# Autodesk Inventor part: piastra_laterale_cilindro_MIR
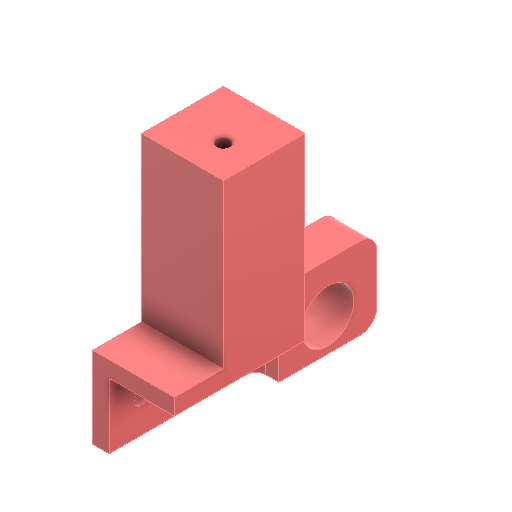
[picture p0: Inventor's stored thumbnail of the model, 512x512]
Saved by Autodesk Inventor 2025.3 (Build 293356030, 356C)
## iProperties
Created: 2025-09
Part Number: piastra_laterale_cilindro_MIR
Material: Plastica ABS
Document SubType Name: Modeling
Designer: R5800u
Density: 1.06 g/cm^3
Appearance: Liscia - Bianco
Author: R5800u
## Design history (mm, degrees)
derived "piastra_laterale_cilindro.ipt"
  sketch "Schizzo1"
    geometry: L1 (2.5, 10)-(-2.5, 10) reference; L2 (-2.5, 10)-(-2.5, -10) reference; L3 (-2.5, -10)-(2.5, -10) reference; L4 (2.5, -10)-(2.5, 10) reference; L5 (2.5, 10)-(-2.5, -10) reference; L6 (-2.5, 10)-(2.5, -10) reference; 1 further point
  sketch "Schizzo2"
    geometry: L1 (-50, 20)-(0, 20) reference; L2 (0, 0)-(-25, 0) reference; L3 (-25, 0)-(-25, 20) reference; L4 (-25, 20)-(0, 20) reference; L5 (0, 20)-(0, 0) reference; L6 (-30, 1)-(-30, 6.7) reference; L7 (-25, 0)-(-30, 0) reference; L8 (-30, 0)-(-30, 20) reference; L9 (-30, 20)-(-25, 20) reference; L10 (-25, 20)-(-25, 0) reference; 1 further point
  sketch "Schizzo3"
    geometry: C1 r 4 at (10, 10) reference; C2 r 8 at (10, 10) reference; 1 further point
  sketch "Schizzo4"
    geometry: L1 (2.5, -10)-(-2.5, -10) reference; L2 (-2.5, -10)-(-2.5, 10) reference; L3 (-2.5, 10)-(2.5, 10) reference; L4 (2.5, 10)-(2.5, -10) reference; 1 further point
feature "Solido1::piastra_laterale_cilindro.ipt"
tag "Lavorazione contrassegno1"
node "Solido1"
